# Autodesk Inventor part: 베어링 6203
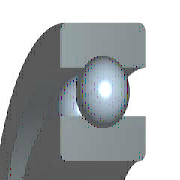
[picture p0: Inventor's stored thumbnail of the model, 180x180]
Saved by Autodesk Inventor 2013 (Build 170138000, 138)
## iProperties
Created: 2012-02
Part Number: 베어링 6203
Material: 강철, 연강
Description: 깊은 그루브 볼 베어링
Document SubType Name: Modeling
Standard: KS B 2023
Designer: mduedu
Standards Organization: KS
Language: ko-KR
Size Designation: 6203 - 17 x 40 x 12
Categories: <MemberInstance><Categories><Category DisplayName="샤프트 부품" InternalName="7f7aeb1f-a693-4053-b835-cee3144e0d98" Mnemonic="SHFT"><Category DisplayName="베어링" Inter
Density: 1 g/cm^3
IsCustomPart: 1
Author: mduedu
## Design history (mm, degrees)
sketch "스케치" dims "d0" = 5.98 (= -0.26 x WD + 0.26 x BD)
  geometry: L1 (3.01, 14.25)-(8.99, 14.25); L2 (6, 14.25)-(6, 11.26); L3 (6, 14.25)-(6, 17.24); L4 (3.778, 12.249)-(0, 12.249); L5 (0, 8.5)-(12, 8.5); L6 (3.778, 16.251)-(0, 16.251); L7 (0, 20)-(12, 20); L8 (12, 8.5)-(12, 12.249); L9 (8.222, 12.249)-(12, 12.249); L10 (8.222, 16.251)-(12, 16.251); L11 (12, 20)-(12, 16.251); L12 (-1.4, 0)-(8.4, 0) reference; L13 (0, -0.3)-(0, 5.3) reference
  constraints: 22 end point, 4 point on line, 2 collinear, 2 perpendicular, 2 symmetric about line, 1 midpoint, 1 parallel, 14 other
  dimensions: "d9" = 17 diameter of L5 L12 (= WD); "d11" = 40 diameter of L7 L12 (= BD); "d12" = 12 distance between parallel lines of L8 L13 (= KB); "d13" = 24.498 diameter of L9 L12 (= 0.326 x BD + 0.674 x WD)
revolve "본체" stored, may be unused: angle "d6" = 90 deg
revolve "볼" stored, may be unused: angle "d7" = 90 deg
pattern_circular "IDS_ARRAYBALL[SIMPL:T]" dims angle "d3" = 360 deg
body "Solid1"
fillet "모깎기1" dims "d1" = 0.6 (= KRS)
other parameters: "WD" = 17 [user parameter; used in 5 equation terms], "BD" = 40 [user parameter; used in 5 equation terms], "KB" = 12 [user parameter; used in 1 equation term], "KRS" = 0.6 [user parameter; used in 1 equation term], "d4" = 0, "d5" = 0, "d8" = 0, "d14" = 0, "d15" = 0, "BBA" = 0 [user parameter], "BC0" = 4750000 [user parameter], "BC" = 9560000 [user parameter], "WR" = 8.5 (= 0.5 x WD) [user parameter]
